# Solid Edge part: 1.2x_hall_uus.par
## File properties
Author: Romil
Template: iso part.par
Last saved by: Romil
Revision: 43
Application: Solid Edge
Accuracy: 0.990
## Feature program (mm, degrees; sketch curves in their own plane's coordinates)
make body feature "unnamed MakeBodyFeature 1"
lofted cutout "unnamed LoftedCutout 1"
replace surface "unnamed ReplaceSurface 1"
sketch for "unnamed RevolvedCutout 1" plane through (0, 0, 0) normal (0, -1, 0) x-axis (1, 0, 0)
  line (1.9, 4.6479) -> (1.9, 3.6)
  line (1.9, 3.6) -> (0.835, 3.6)
  arc centre (0.835, 3.4) radius 0.2 from (0.635, 3.4) to (0.835, 3.6) cw
  line (0.635, 3.05) -> (0.635, 3.4)
  arc centre (0.335, 3.05) radius 0.3 from (0.335, 2.75) to (0.635, 3.05) ccw
  line (0.335, 2.75) -> (-0.335, 2.75)
  arc centre (-0.335, 3.05) radius 0.3 from (-0.335, 2.75) to (-0.635, 3.05) cw
  line (-0.635, 3.05) -> (-0.635, 3.4)
  arc centre (-0.835, 3.4) radius 0.2 from (-0.835, 3.6) to (-0.635, 3.4) cw
  line (-0.835, 3.6) -> (-1.9, 3.6)
  line (-1.9, 4.6479) -> (-1.9, 3.6)
  line (-1.9, 4.6479) -> (1.9, 4.6479)
revolve "unnamed RevolvedCutout 1" cut finite 360 deg
fillet "unnamed Round 1"
Other named dimensions: "KeypointCurve_5": StartDerivMagnitude = -1.9 mm; EndDerivMagnitude = -1.9 mm | "ExtrudedSurface_1": FiniteDepth = 40.6235 mm
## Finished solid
Body 1: sheet body, 1 face, 4 edges, 4 vertices.
  Faces by surface: plane 1
  Edges by curve: line 4
Body 2: solid body, 29 faces, 60 edges, 32 vertices.
  Faces by surface: plane 12, cylinder 11, torus 6
  Edges by curve: line 32, circle 28
Body 3: solid body, 3 faces, 2 edges, 0 vertices.
  Faces by surface: plane 2, cylinder 1
  Edges by curve: circle 2
Bounding box of the edges (mm; curved faces can reach further): 8.406 x 27.614 x 40.623, from (-1.9, -11.5357, -20.3117) to (6.5058, 16.0781, 20.3117).
Cylindrical faces by radius (mm): R0.15 x2, R0.9025 x2, R2.55 x4, R2.75 x1, R3.6 x3
Toroidal faces (ring radius, tube radius in mm): R3.05 r0.3 x2, R3.4 r0.2 x4
Planar faces by outward normal: +x 3, +y 1, +z 1, -x 3, -y 1, -z 1, oblique 4
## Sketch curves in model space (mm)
line (1.9, 16.0781, 0) -> (1.9, -11.5357, 0)
arc centre (6.5058, 1.8031, -1.8031) radius 0.9025 from (6.5058, 0.9006, -1.8031) through (6.5058, 1.1838, -1.1467) to (6.5058, 1.8031, -0.9006)
line (6.5058, 1.8031, -0.9006) -> (6.5058, 2.3857, -0.9006)
arc centre (6.5058, 0, 0) radius 2.55 from (6.5058, 1.9061, 1.6939) through (6.5058, 2.5075, 0.4635) to (6.5058, 2.3857, -0.9006)
line (6.5058, 1.9061, 1.6939) -> (6.5058, 1.2728, 1.0607)
arc centre (6.5058, 1.1667, 1.1667) radius 0.15 from (6.5058, 1.2728, 1.0607) through (6.5058, 1.0576, 1.0638) to (6.5058, 1.0607, 1.2728)
line (6.5058, 1.0607, 1.2728) -> (6.5058, 1.6939, 1.9061)
arc centre (6.5058, 0, 0) radius 2.55 from (6.5058, -0.9006, 2.3857) through (6.5058, 0.4635, 2.5075) to (6.5058, 1.6939, 1.9061)
line (6.5058, -0.9006, 2.3857) -> (6.5058, -0.9006, 1.8031)
arc centre (6.5058, -1.8031, 1.8031) radius 0.9025 from (6.5058, -0.9006, 1.8031) through (6.5058, -1.1838, 1.1467) to (6.5058, -1.8031, 0.9006)
line (6.5058, -1.8031, 0.9006) -> (6.5058, -2.3857, 0.9006)
arc centre (6.5058, 0, 0) radius 2.55 from (6.5058, -1.9061, -1.6939) through (6.5058, -2.5075, -0.4635) to (6.5058, -2.3857, 0.9006)
line (6.5058, -1.9061, -1.6939) -> (6.5058, -1.2728, -1.0607)
arc centre (6.5058, -1.1667, -1.1667) radius 0.15 from (6.5058, -1.2728, -1.0607) through (6.5058, -1.0576, -1.0638) to (6.5058, -1.0607, -1.2728)
line (6.5058, -1.0607, -1.2728) -> (6.5058, -1.6939, -1.9061)
arc centre (6.5058, 0, 0) radius 2.55 from (6.5058, 0.9006, -2.3857) through (6.5058, -0.4635, -2.5075) to (6.5058, -1.6939, -1.9061)
line (6.5058, 0.9006, -2.3857) -> (6.5058, 0.9006, -1.8031)
circle centre (6.5058, 0, 0) radius 3.6
line (1.9, 0, -9.5321) -> (1.9, 0, 12.9089)
line (-1.9, 0, 9.7506) -> (-1.9, 0, -7.9529)
circle centre (-1.9, 0, 0) radius 3.6
circle centre (1.9, 0, 0) radius 3.6
line (-2.4774, 0, 0) -> (5.0483, 0, 0)
arc centre (-0.335, 0, 3.05) radius 0.3 from (-0.335, 0, 2.75) through (-0.5532, 0, 2.8441) to (-0.635, 0, 3.05)
line (-0.635, 0, 3.05) -> (-0.635, 0, 3.4)
arc centre (-0.835, 0, 3.4) radius 0.2 from (-0.835, 0, 3.6) through (-0.6895, 0, 3.5372) to (-0.635, 0, 3.4)
line (-0.835, 0, 3.6) -> (-1.9, 0, 3.6)
line (-1.9, 0, 4.6479) -> (-1.9, 0, 3.6)
line (-1.9, 0, 4.6479) -> (1.9, 0, 4.6479)
line (1.9, 0, 4.6479) -> (1.9, 0, 3.6)
line (1.9, 0, 3.6) -> (0.835, 0, 3.6)
arc centre (0.835, 0, 3.4) radius 0.2 from (0.635, 0, 3.4) through (0.6978, 0, 3.5455) to (0.835, 0, 3.6)
line (0.635, 0, 3.05) -> (0.635, 0, 3.4)
arc centre (0.335, 0, 3.05) radius 0.3 from (0.335, 0, 2.75) through (0.5532, 0, 2.8441) to (0.635, 0, 3.05)
line (0.335, 0, 2.75) -> (-0.335, 0, 2.75)
circle centre (0, 0, 0) radius 2.55
circle centre (0, 0, 0) radius 3.6
arc centre (0, 0, 0) radius 2.55 from (0, -2.5456, 0.15) through (0, -2.494, 0.5314) to (0, -2.3857, 0.9006)
line (0, -1.8031, 0.9006) -> (0, -2.3857, 0.9006)
arc centre (0, 0, 0) radius 2.55 from (0, -1.9061, -1.6939) through (0, -2.5075, -0.4635) to (0, -2.3857, 0.9006)
line (0, -1.9061, -1.6939) -> (0, -1.2728, -1.0607)
arc centre (0, -1.1667, -1.1667) radius 0.15 from (0, -1.2728, -1.0607) through (0, -1.0576, -1.0638) to (0, -1.0607, -1.2728)
line (0, -1.0607, -1.2728) -> (0, -1.6939, -1.9061)
arc centre (0, 0, 0) radius 2.55 from (0, 0.9006, -2.3857) through (0, -0.4635, -2.5075) to (0, -1.6939, -1.9061)
line (0, 0.9006, -2.3857) -> (0, 0.9006, -1.8031)
arc centre (0, 1.8031, -1.8031) radius 0.9025 from (0, 0.9006, -1.8031) through (0, 1.1838, -1.1467) to (0, 1.8031, -0.9006)
line (0, 1.8031, -0.9006) -> (0, 2.3857, -0.9006)
arc centre (0, 0, 0) radius 2.55 from (0, 1.9061, 1.6939) through (0, 2.5075, 0.4635) to (0, 2.3857, -0.9006)
line (0, 1.9061, 1.6939) -> (0, 1.2728, 1.0607)
arc centre (0, 1.1667, 1.1667) radius 0.15 from (0, 1.2728, 1.0607) through (0, 1.0576, 1.0638) to (0, 1.0607, 1.2728)
line (0, 1.0607, 1.2728) -> (0, 1.6939, 1.9061)
arc centre (0, 0, 0) radius 2.55 from (0, -0.9006, 2.3857) through (0, 0.4635, 2.5075) to (0, 1.6939, 1.9061)
line (0, -0.9006, 2.3857) -> (0, -0.9006, 1.8031)
arc centre (0, -1.8031, 1.8031) radius 0.9025 from (0, -0.9006, 1.8031) through (0, -1.1838, 1.1467) to (0, -1.8031, 0.9006)
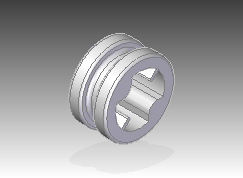
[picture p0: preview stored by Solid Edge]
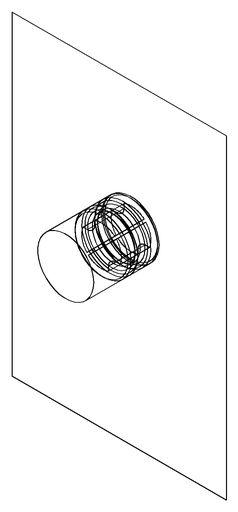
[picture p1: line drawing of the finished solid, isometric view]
